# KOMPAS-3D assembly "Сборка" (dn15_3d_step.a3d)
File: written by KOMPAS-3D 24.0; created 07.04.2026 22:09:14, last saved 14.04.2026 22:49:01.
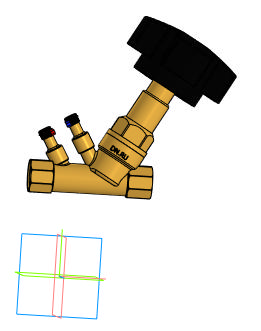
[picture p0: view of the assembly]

Document properties: Автор: tyuri; Полное имя файла: D:\Аутсорс\VB0000P-T Клапан балансировочный статический DN.ru\DN15\Исходные файлы\dn15_3d_step.a3d

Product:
- Component [detail]: Деталь1  | qty 1  | Масса: 0.341211; Автор: tyuri; additional columns: Типовые; source file: Деталь1 - Деталь1.m3d
- Component [detail]: Деталь2  | qty 1  | Масса: 0.541971; Автор: tyuri; source file: Деталь2 - Деталь2.m3d
- Part/product: Сборка
    Масса: 0.883181

Referenced files in D:\Аутсорс\VB0000P-T Клапан балансировочный статический DN.ru\DN15\Исходные файлы\: Деталь1 - Деталь1.m3d, Деталь2 - Деталь2.m3d
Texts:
  Деталь1 Деталь1
  Деталь2 Деталь2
